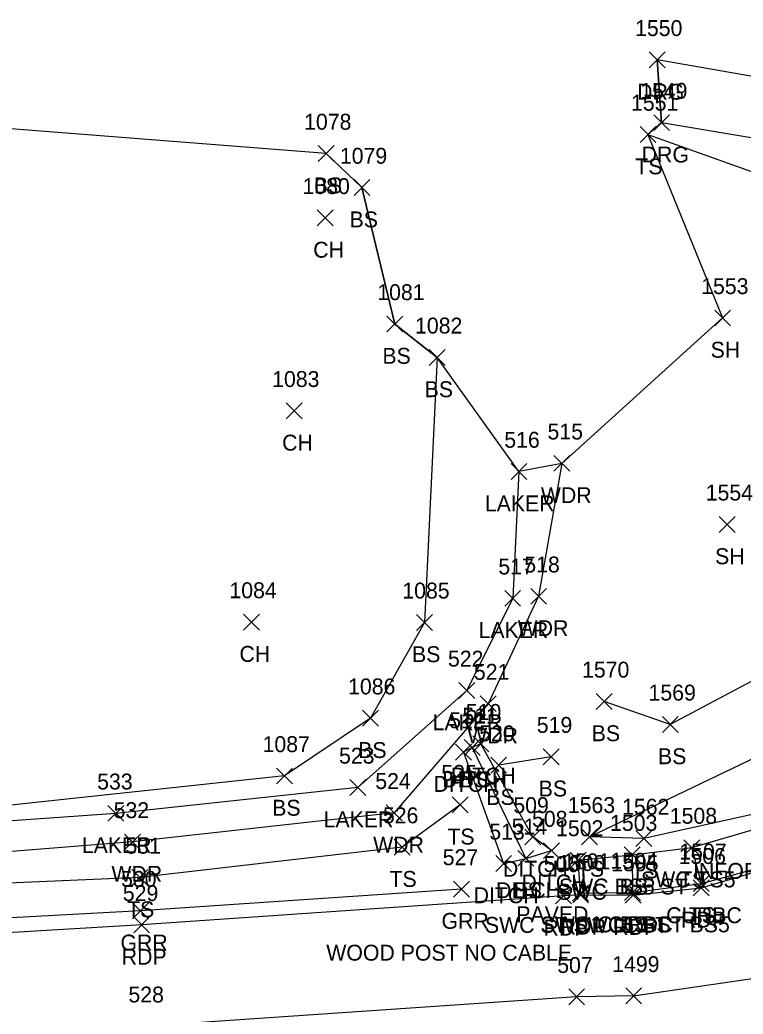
# Model space of a CAD drawing. Extents: x 1716490 to 1717645, y 888034 to 890004.
# Drawn here: x 1717358.9 to 1717449.9, y 888260.7 to 888385.7 of the extents above; entities that cross this region are included whole.
import ezdxf

# ---------------------------------------------------------------- set-up
doc = ezdxf.new("R2010")
doc.units = 0
for name, color, linetype in [('D_A', 7, 'Continuous'), ('D_C', 7, 'Continuous'), ('D_I', 7, 'Continuous'), ('D_TIC', 7, 'Continuous'), ('DD', 7, 'Continuous'), ('L_A', 7, 'Continuous'), ('L_I', 7, 'Continuous'), ('L_TIC', 7, 'Continuous'), ('LAWA', 7, 'Continuous'), ('LAWE', 7, 'Continuous'), ('LELB', 7, 'Continuous'), ('LSOGP', 7, 'Continuous'), ('P_A', 7, 'Continuous'), ('P_I', 7, 'Continuous'), ('P_TIC', 7, 'Continuous'), ('PET', 7, 'Continuous'), ('PRC', 7, 'Continuous'), ('R_A', 7, 'Continuous'), ('R_C', 7, 'Continuous'), ('R_I', 7, 'Continuous'), ('R_TIC', 7, 'Continuous'), ('RC', 7, 'Continuous'), ('RDG', 7, 'Continuous'), ('RGR', 7, 'Continuous'), ('RSW', 7, 'Continuous'), ('S_C', 7, 'Continuous')]:
    doc.layers.add(name, color=color, linetype=linetype)

msp = doc.modelspace()

# ---------------------------------------------------------------- linework, layer by layer
at = {"layer": 'D_TIC'}
for points in [[(1717414.79, 888293.22), (1717416.79, 888295.22)], [(1717416.79, 888293.22), (1717414.79, 888295.22)], [(1717415.87, 888293.7), (1717417.87, 888295.7)], [(1717417.87, 888293.7), (1717415.87, 888295.7)], [(1717413.7, 888292.65), (1717415.7, 888294.65)], [(1717415.7, 888292.65), (1717413.7, 888294.65)], [(1717422.42, 888281.98), (1717424.42, 888283.98)], [(1717424.42, 888281.98), (1717422.42, 888283.98)], [(1717421.55, 888279.29), (1717423.55, 888281.29)], [(1717423.55, 888279.29), (1717421.55, 888281.29)], [(1717424.76, 888280.26), (1717426.76, 888282.26)], [(1717426.76, 888280.26), (1717424.76, 888282.26)], [(1717418.75, 888278.65), (1717420.75, 888280.65)], [(1717420.75, 888278.65), (1717418.75, 888280.65)]]:
    msp.add_lwpolyline(points, dxfattribs=at)
at = {"layer": 'DD'}
msp.add_lwpolyline([(1717425.76, 888281.26), (1717423.42, 888282.98), (1717416.87, 888294.7), (1717415.79, 888294.22), (1717414.7, 888293.65), (1717419.75, 888279.65), (1717422.55, 888280.29)], dxfattribs=at)
at = {"layer": 'L_TIC'}
for points in [[(1717436.9, 888370.3), (1717438.9, 888372.3)], [(1717438.9, 888370.3), (1717436.9, 888372.3)], [(1717396.44, 888367.91), (1717398.44, 888369.91)], [(1717398.44, 888367.91), (1717396.44, 888369.91)], [(1717400.94, 888363.63), (1717402.94, 888365.63)], [(1717402.94, 888363.63), (1717400.94, 888365.63)], [(1717396.32, 888359.82), (1717398.32, 888361.82)], [(1717398.32, 888359.82), (1717396.32, 888361.82)], [(1717446.29, 888347.24), (1717448.29, 888349.24)], [(1717448.29, 888347.24), (1717446.29, 888349.24)], [(1717405.07, 888346.48), (1717407.07, 888348.48)], [(1717407.07, 888346.48), (1717405.07, 888348.48)], [(1717410.38, 888342.28), (1717412.38, 888344.28)], [(1717412.38, 888342.28), (1717410.38, 888344.28)], [(1717392.42, 888335.56), (1717394.42, 888337.56)], [(1717394.42, 888335.56), (1717392.42, 888337.56)], [(1717420.68, 888327.92), (1717422.68, 888329.92)], [(1717422.68, 888327.92), (1717420.68, 888329.92)], [(1717426.07, 888328.96), (1717428.07, 888330.96)], [(1717428.07, 888328.96), (1717426.07, 888330.96)], [(1717446.85, 888321.28), (1717448.85, 888323.28)], [(1717448.85, 888321.28), (1717446.85, 888323.28)], [(1717419.89, 888311.99), (1717421.89, 888313.99)], [(1717421.89, 888311.99), (1717419.89, 888313.99)], [(1717423.15, 888312.24), (1717425.15, 888314.24)], [(1717425.15, 888312.24), (1717423.15, 888314.24)], [(1717387.04, 888309), (1717389.04, 888311)], [(1717389.04, 888309), (1717387.04, 888311)], [(1717408.79, 888308.96), (1717410.79, 888310.96)], [(1717410.79, 888308.96), (1717408.79, 888310.96)], [(1717414.11, 888300.4), (1717416.11, 888302.4)], [(1717416.11, 888300.4), (1717414.11, 888302.4)], [(1717416.81, 888298.74), (1717418.81, 888300.74)], [(1717418.81, 888298.74), (1717416.81, 888300.74)], [(1717431.39, 888299.02), (1717433.39, 888301.02)], [(1717433.39, 888299.02), (1717431.39, 888301.02)], [(1717402.02, 888296.91), (1717404.02, 888298.91)], [(1717404.02, 888296.91), (1717402.02, 888298.91)], [(1717439.71, 888296.13), (1717441.71, 888298.13)], [(1717441.71, 888296.13), (1717439.71, 888298.13)], [(1717414.79, 888293.22), (1717416.79, 888295.22)], [(1717416.79, 888293.22), (1717414.79, 888295.22)], [(1717424.72, 888292.07), (1717426.72, 888294.07)], [(1717426.72, 888292.07), (1717424.72, 888294.07)], [(1717418.13, 888291.01), (1717420.13, 888293.01)], [(1717420.13, 888291.01), (1717418.13, 888293.01)], [(1717391.21, 888289.65), (1717393.21, 888291.65)], [(1717393.21, 888289.65), (1717391.21, 888291.65)], [(1717400.41, 888288.2), (1717402.41, 888290.2)], [(1717402.41, 888288.2), (1717400.41, 888290.2)], [(1717413.27, 888286.03), (1717415.27, 888288.03)], [(1717415.27, 888286.03), (1717413.27, 888288.03)], [(1717370, 888284.95), (1717372, 888286.95)], [(1717372, 888284.95), (1717370, 888286.95)], [(1717404.98, 888285.01), (1717406.98, 888287.01)], [(1717406.98, 888285.01), (1717404.98, 888287.01)], [(1717429.56, 888281.99), (1717431.56, 888283.99)], [(1717431.56, 888281.99), (1717429.56, 888283.99)], [(1717429.56, 888281.99), (1717431.56, 888283.99)], [(1717431.56, 888281.99), (1717429.56, 888283.99)], [(1717436.38, 888281.78), (1717438.38, 888283.78)], [(1717438.38, 888281.78), (1717436.38, 888283.78)], [(1717372.07, 888281.35), (1717374.07, 888283.35)], [(1717374.07, 888281.35), (1717372.07, 888283.35)], [(1717405.99, 888280.7), (1717407.99, 888282.7)], [(1717407.99, 888280.7), (1717405.99, 888282.7)], [(1717442.41, 888280.64), (1717444.41, 888282.64)], [(1717444.41, 888280.64), (1717442.41, 888282.64)], [(1717421.55, 888279.29), (1717423.55, 888281.29)], [(1717423.55, 888279.29), (1717421.55, 888281.29)], [(1717434.9, 888279.75), (1717436.9, 888281.75)], [(1717436.9, 888279.75), (1717434.9, 888281.75)], [(1717372.99, 888276.88), (1717374.99, 888278.88)], [(1717374.99, 888276.88), (1717372.99, 888278.88)], [(1717443.61, 888276.14), (1717445.61, 888278.14)], [(1717445.61, 888276.14), (1717443.61, 888278.14)], [(1717434.94, 888274.99), (1717436.94, 888276.99)], [(1717436.94, 888274.99), (1717434.94, 888276.99)]]:
    msp.add_lwpolyline(points, dxfattribs=at)
at = {"layer": 'LAWA'}
msp.add_lwpolyline([(1717427.07, 888329.96), (1717424.15, 888313.24), (1717417.81, 888299.74), (1717405.98, 888286.01), (1717373.07, 888282.35), (1717318.58, 888278), (1717270.11, 888276.06), (1717231.85, 888274.55), (1717204.52, 888271.65)], dxfattribs=at)
at = {"layer": 'LAWE'}
msp.add_lwpolyline([(1717421.68, 888328.92), (1717420.89, 888312.99), (1717415.11, 888301.4), (1717401.41, 888289.2), (1717371, 888285.95), (1717321.69, 888282.44), (1717271.81, 888279.67), (1717230.21, 888280.53), (1717194.5, 888279.04), (1717177.12, 888274.47), (1717174.06, 888271.23), (1717172.86, 888266.22)], dxfattribs=at)
at = {"layer": 'LELB'}
for points in [[(1717437.9, 888371.3), (1717480.12, 888356.2), (1717485.27, 888337.4), (1717487.29, 888323.09), (1717480.33, 888308.38), (1717466.83, 888293.35), (1717453.47, 888286.33), (1717437.38, 888282.78), (1717430.56, 888282.99)], [(1717397.44, 888368.91), (1717401.94, 888364.63), (1717406.07, 888347.48), (1717411.38, 888343.28), (1717409.79, 888309.96), (1717403.02, 888297.91), (1717392.21, 888290.65), (1717353.83, 888286.56), (1717306.03, 888285.64), (1717272.45, 888283.32), (1717220.2, 888284.1), (1717193.83, 888280.31), (1717176.82, 888276.72), (1717169.82, 888270.77)], [(1717485.27, 888337.4), (1717466.59, 888318.08), (1717457.73, 888306.17), (1717440.71, 888297.13), (1717432.39, 888300.02)], [(1717430.56, 888282.99), (1717454.59, 888294.53), (1717466.79, 888305.27), (1717473.31, 888317.87)], [(1717415.79, 888294.22), (1717422.55, 888280.29)], [(1717425.72, 888293.07), (1717419.13, 888292.01)], [(1717414.27, 888287.03), (1717406.99, 888281.7), (1717373.99, 888277.88), (1717318.52, 888275.5), (1717269.66, 888272.61), (1717230.91, 888271.26), (1717203.91, 888268.9), (1717185.06, 888265.29), (1717179.22, 888264.43), (1717179.32, 888261.72)], [(1717422.55, 888280.29), (1717425.76, 888281.26)], [(1717444.61, 888277.14), (1717443.41, 888281.64)], [(1717435.9, 888280.75), (1717435.94, 888275.99)]]:
    msp.add_lwpolyline(points, dxfattribs=at)
at = {"layer": 'LSOGP'}
msp.add_lwpolyline([(1717522.62, 888364.73), (1717495.01, 888370.94), (1717439.06, 888380.69), (1717439.62, 888372.79), (1717437.9, 888371.3), (1717447.29, 888348.24), (1717427.07, 888329.96), (1717421.68, 888328.92), (1717411.38, 888343.28), (1717406.07, 888347.48), (1717401.94, 888364.63), (1717397.44, 888368.91), (1717347.56, 888372.82)], dxfattribs=at)
at = {"layer": 'P_TIC'}
for points in [[(1717443.58, 888275.58), (1717445.58, 888277.58)], [(1717445.58, 888275.58), (1717443.58, 888277.58)], [(1717426.27, 888274.57), (1717428.27, 888276.57)], [(1717428.27, 888274.57), (1717426.27, 888276.57)], [(1717428.44, 888274.7), (1717430.44, 888276.7)], [(1717430.44, 888274.7), (1717428.44, 888276.7)], [(1717435.04, 888274.67), (1717437.04, 888276.67)], [(1717437.04, 888274.67), (1717435.04, 888276.67)], [(1717373.24, 888270.92), (1717375.24, 888272.92)], [(1717375.24, 888270.92), (1717373.24, 888272.92)], [(1717427.93, 888261.88), (1717429.93, 888263.88)], [(1717429.93, 888261.88), (1717427.93, 888263.88)], [(1717435.1, 888261.99), (1717437.1, 888263.99)], [(1717437.1, 888261.99), (1717435.1, 888263.99)]]:
    msp.add_lwpolyline(points, dxfattribs=at)
at = {"layer": 'PET'}
for points in [[(1717429.44, 888275.7), (1717436.04, 888275.67), (1717444.58, 888276.58), (1717456, 888279.92), (1717471.01, 888288.31), (1717478.45, 888294.9), (1717483.54, 888300.72), (1717490.31, 888311.04), (1717493.61, 888318.94), (1717495.84, 888328.12), (1717495.49, 888342.35), (1717495.55, 888342.67), (1717495.05, 888362.52), (1717495.01, 888370.94)], [(1717427.27, 888275.57), (1717374.24, 888271.92), (1717317.86, 888268.58), (1717270, 888265.54), (1717231.18, 888263.33), (1717177.06, 888260.69), (1717177.8, 888248.05), (1717178.6, 888236.51), (1717214.03, 888237.98), (1717254.52, 888239.74), (1717289.28, 888241.31), (1717339.42, 888243.96), (1717387.67, 888246.79), (1717419.3, 888248.63), (1717429.05, 888249.53)], [(1717429.44, 888275.7), (1717427.27, 888275.57)]]:
    msp.add_lwpolyline(points, dxfattribs=at)
at = {"layer": 'PRC'}
for points in [[(1717436.1, 888262.99), (1717458.49, 888266.27), (1717492.01, 888269.4), (1717536.7, 888274.82), (1717555.46, 888275.73), (1717587.78, 888278.25), (1717619.44, 888277.12), (1717629.03, 888277.17)], [(1717428.93, 888262.88), (1717374.93, 888259.17), (1717318.78, 888255.52), (1717271.43, 888252.69), (1717231.27, 888251.09), (1717177.8, 888248.05)], [(1717436.1, 888262.99), (1717428.93, 888262.88)]]:
    msp.add_lwpolyline(points, dxfattribs=at)
at = {"layer": 'R_TIC'}
for points in [[(1717438.06, 888379.69), (1717440.06, 888381.69)], [(1717440.06, 888379.69), (1717438.06, 888381.69)], [(1717438.62, 888371.79), (1717440.62, 888373.79)], [(1717440.62, 888371.79), (1717438.62, 888373.79)], [(1717442.41, 888280.64), (1717444.41, 888282.64)], [(1717444.41, 888280.64), (1717442.41, 888282.64)], [(1717434.9, 888279.75), (1717436.9, 888281.75)], [(1717436.9, 888279.75), (1717434.9, 888281.75)], [(1717428.11, 888279.08), (1717430.11, 888281.08)], [(1717430.11, 888279.08), (1717428.11, 888281.08)], [(1717413.46, 888275.43), (1717415.46, 888277.43)], [(1717415.46, 888275.43), (1717413.46, 888277.43)], [(1717443.61, 888276.14), (1717445.61, 888278.14)], [(1717445.61, 888276.14), (1717443.61, 888278.14)], [(1717428.42, 888274.92), (1717430.42, 888276.92)], [(1717430.42, 888274.92), (1717428.42, 888276.92)], [(1717428.42, 888274.92), (1717430.42, 888276.92)], [(1717430.42, 888274.92), (1717428.42, 888276.92)], [(1717434.94, 888274.99), (1717436.94, 888276.99)], [(1717436.94, 888274.99), (1717434.94, 888276.99)], [(1717434.94, 888274.99), (1717436.94, 888276.99)], [(1717436.94, 888274.99), (1717434.94, 888276.99)], [(1717373.09, 888272.7), (1717375.09, 888274.7)], [(1717375.09, 888272.7), (1717373.09, 888274.7)]]:
    msp.add_lwpolyline(points, dxfattribs=at)
at = {"layer": 'RC'}
msp.add_lwpolyline([(1717435.94, 888275.99), (1717444.61, 888277.14), (1717455.98, 888280.23), (1717470.62, 888288.38), (1717478.24, 888295.11), (1717483.24, 888300.87), (1717490.14, 888311.11), (1717493.43, 888318.97), (1717495.63, 888328.58), (1717495.65, 888328.57)], dxfattribs=at)
at = {"layer": 'RDG'}
msp.add_lwpolyline([(1717488.53, 888362.4), (1717485.42, 888364.27), (1717462.66, 888368.93), (1717439.62, 888372.79), (1717439.06, 888380.69)], dxfattribs=at)
at = {"layer": 'RGR'}
msp.add_lwpolyline([(1717414.46, 888276.43), (1717374.09, 888273.7), (1717318.26, 888270.69), (1717269.91, 888267.54), (1717230.71, 888265.34), (1717183.33, 888262.06)], dxfattribs=at)
at = {"layer": 'RSW'}
for points in [[(1717429.42, 888275.92), (1717429.11, 888280.08), (1717435.9, 888280.75), (1717443.41, 888281.64), (1717454.06, 888284.75), (1717467.58, 888292.11), (1717474.95, 888298.71), (1717480.12, 888304.72), (1717485.9, 888313.6), (1717488.98, 888320.65), (1717490.99, 888328.72), (1717490.36, 888341.91), (1717495.36, 888342.17), (1717495.65, 888328.57)], [(1717429.42, 888275.92), (1717435.94, 888275.99)]]:
    msp.add_lwpolyline(points, dxfattribs=at)

# ---------------------------------------------------------------- texts
at = {"layer": 'D_A'}
for p in [(1717412.02, 888289.22), (1717413.11, 888289.7), (1717410.93, 888288.65), (1717419.66, 888277.98), (1717422, 888276.26), (1717415.98, 888274.65), (1717418.79, 888275.29)]:
    msp.add_text('DITCH', height=2, dxfattribs=at).set_placement(p)
at = {"layer": 'D_C'}
msp.add_text('PAVED', height=2, dxfattribs=at).set_placement((1717421.35, 888272.26))
at = {"layer": 'D_I'}
for s, p in [('512', (1717412.9, 888296.65)), ('511', (1717414.56, 888297.22)), ('510', (1717414.99, 888297.7)), ('509', (1717420.97, 888285.98)), ('508', (1717423.32, 888284.26)), ('514', (1717420.76, 888283.29)), ('513', (1717417.95, 888282.65))]:
    msp.add_text(s, height=2, dxfattribs=at).set_placement(p)
at = {"layer": 'L_A'}
for s, p in [('TS', (1717436.31, 888366.3)), ('BS', (1717395.88, 888363.91)), ('BS', (1717400.38, 888359.63)), ('CH', (1717395.81, 888355.82)), ('SH', (1717445.78, 888343.24)), ('BS', (1717404.51, 888342.48)), ('BS', (1717409.82, 888338.28)), ('CH', (1717391.9, 888331.56)), ('WDR', (1717424.43, 888324.96)), ('LAKER', (1717417.39, 888323.92)), ('SH', (1717446.34, 888317.28)), ('LAKER', (1717416.59, 888307.99)), ('WDR', (1717421.51, 888308.24)), ('CH', (1717386.53, 888305)), ('BS', (1717408.23, 888304.96)), ('LAKER', (1717410.82, 888296.4)), ('WDR', (1717415.17, 888294.74)), ('BS', (1717430.83, 888295.02)), ('BS', (1717401.46, 888292.91)), ('BS', (1717439.16, 888292.13)), ('BS', (1717414.23, 888289.22)), ('BS', (1717424.16, 888288.07)), ('BS', (1717417.57, 888287.01)), ('BS', (1717390.65, 888285.65)), ('LAKER', (1717397.12, 888284.2)), ('TS', (1717412.68, 888282.03)), ('LAKER', (1717366.71, 888280.95)), ('WDR', (1717403.34, 888281.01)), ('TS', (1717428.97, 888277.99)), ('TS', (1717428.97, 888277.99)), ('WDR', (1717370.43, 888277.35)), ('TS', (1717405.4, 888276.7)), ('TS', (1717435.79, 888277.78)), ('TS', (1717441.82, 888276.64)), ('BS', (1717434.34, 888275.75)), ('BS', (1717420.99, 888275.29)), ('TS', (1717372.4, 888272.88)), ('TS', (1717443.02, 888272.14)), ('BS', (1717434.38, 888270.99))]:
    msp.add_text(s, height=2, dxfattribs=at).set_placement(p)
at = {"layer": 'L_I'}
for s, p in [('1551', (1717435.77, 888374.3)), ('1078', (1717394.66, 888371.91)), ('1079', (1717399.16, 888367.63)), ('1080', (1717394.46, 888363.82)), ('1081', (1717403.86, 888350.48)), ('1553', (1717444.59, 888351.24)), ('1082', (1717408.61, 888346.28)), ('1083', (1717390.64, 888339.56)), ('515', (1717425.27, 888332.96)), ('516', (1717419.83, 888331.92)), ('1554', (1717445.16, 888325.28)), ('517', (1717419.09, 888315.99)), ('518', (1717422.35, 888316.24)), ('1084', (1717385.27, 888313)), ('1085', (1717407.01, 888312.96)), ('522', (1717412.75, 888304.4)), ('1570', (1717429.61, 888303.02)), ('521', (1717416.01, 888302.74)), ('1086', (1717400.19, 888300.91)), ('1569', (1717437.97, 888300.13)), ('511', (1717414.56, 888297.22)), ('519', (1717423.92, 888296.07)), ('520', (1717416.68, 888295.01)), ('1087', (1717389.44, 888293.65)), ('523', (1717399.05, 888292.2)), ('525', (1717411.91, 888290.03)), ('533', (1717368.64, 888288.95)), ('524', (1717403.61, 888289.01)), ('532', (1717370.71, 888285.35)), ('1563', (1717427.82, 888285.99)), ('1563', (1717427.82, 888285.99)), ('1562', (1717434.64, 888285.78)), ('526', (1717404.57, 888284.7)), ('1508', (1717440.64, 888284.64)), ('514', (1717420.76, 888283.29)), ('1503', (1717433.13, 888283.75)), ('531', (1717372.19, 888280.88)), ('1507', (1717441.84, 888280.14)), ('1504', (1717433.17, 888278.99))]:
    msp.add_text(s, height=2, dxfattribs=at).set_placement(p)
at = {"layer": 'P_A'}
for p in [(1717424.76, 888270.57), (1717426.93, 888270.7), (1717433.53, 888270.67), (1717442.06, 888271.58), (1717371.73, 888266.92)]:
    msp.add_text('RDP', height=2, dxfattribs=at).set_placement(p)
at = {"layer": 'P_I'}
for s, p in [('1506', (1717441.75, 888279.58)), ('506', (1717424.78, 888278.57)), ('1500', (1717426.58, 888278.7)), ('1505', (1717433.27, 888278.67)), ('529', (1717371.87, 888274.92)), ('507', (1717426.49, 888265.88)), ('1499', (1717433.4, 888265.99)), ('528', (1717372.57, 888262.17))]:
    msp.add_text(s, height=2, dxfattribs=at).set_placement(p)
at = {"layer": 'R_A'}
for s, p in [('DRG', (1717436.54, 888375.69)), ('DRG', (1717437.11, 888367.79)), ('SWC TS5', (1717437.02, 888276.64)), ('SWC BS5 ST', (1717426.71, 888275.75)), ('SWC', (1717426.48, 888275.08)), ('CURBC', (1717440.19, 888272.14)), ('GRR', (1717411.94, 888271.43)), ('SWC ST SWC1 ST', (1717417.4, 888270.92)), ('SWC ST SWC1 ST', (1717417.4, 888270.92)), ('SWC1 CC1 ST BS5', (1717424.41, 888270.99)), ('CURBC', (1717431.52, 888270.99)), ('GRR', (1717371.57, 888268.7))]:
    msp.add_text(s, height=2, dxfattribs=at).set_placement(p)
at = {"layer": 'R_C'}
msp.add_text('WOOD POST NO CABLE', height=2, dxfattribs=at).set_placement((1717397.45, 888267.43))
at = {"layer": 'R_I'}
for s, p in [('1550', (1717436.28, 888383.69)), ('1549', (1717436.92, 888375.79)), ('1508', (1717440.64, 888284.64)), ('1502', (1717426.34, 888283.08)), ('1503', (1717433.13, 888283.75)), ('527', (1717412.09, 888279.43)), ('1507', (1717441.84, 888280.14)), ('1501', (1717427.22, 888278.92)), ('1501', (1717427.22, 888278.92)), ('1504', (1717433.17, 888278.99)), ('1504', (1717433.17, 888278.99)), ('530', (1717371.64, 888276.7))]:
    msp.add_text(s, height=2, dxfattribs=at).set_placement(p)
at = {"layer": 'S_C'}
msp.add_text('INFORMATION', height=2, dxfattribs=at).set_placement((1717443.57, 888277.71))

doc.saveas('drawing.dxf')
